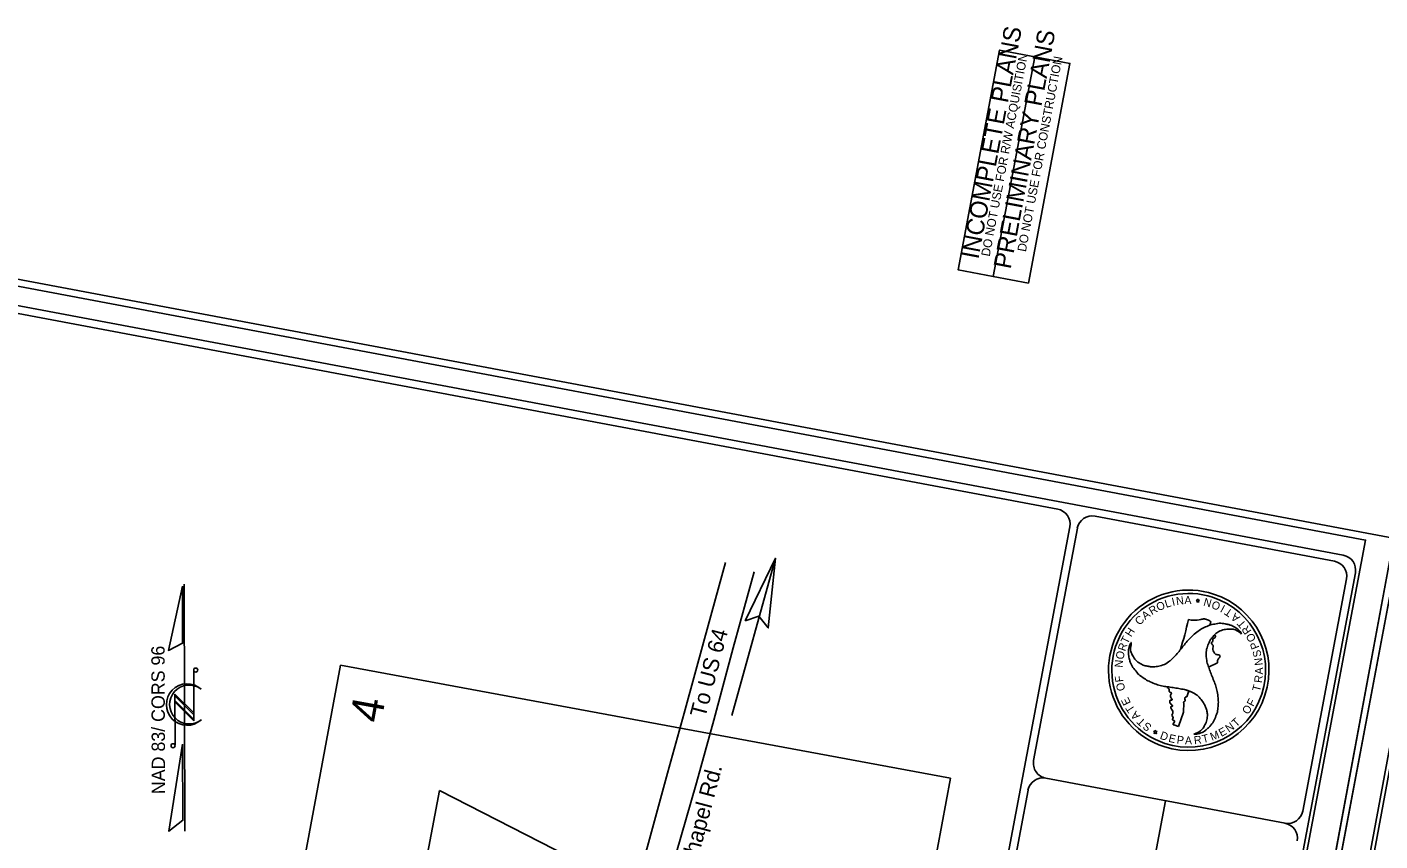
# Model space of a CAD drawing. Extents: x 1665923 to 1668724, y 690926 to 694920.
# Drawn here: x 1666413 to 1667302, y 692584 to 693119 of the extents above; entities that cross this region are included whole.
import ezdxf

# ---------------------------------------------------------------- set-up
doc = ezdxf.new("R2010")
doc.units = 0
for name, color, linetype in [('Default', 7, 'Continuous'), ('Prop Dimension Text', 7, 'Continuous'), ('Prop Horizontal Alignment Curve and Spiral Data', 7, 'Continuous'), ('Prop Terminator CELL', 7, 'Continuous'), ('Sheet Cutting Line CELL', 7, 'Continuous'), ('Sheet North Arrow CELL', 7, 'Continuous'), ('Sheet Plot Border Inside CELL', 7, 'Continuous'), ('Sheet Plot Border Outside CELL', 7, 'Continuous'), ('Sheet Sticker Incomplete CELL', 7, 'Continuous'), ('Sheet Sticker Preliminary CELL', 7, 'Continuous'), ('Sheet Symbology CELL', 7, 'Continuous'), ('Sheet Title CELL', 7, 'Continuous')]:
    doc.layers.add(name, color=color, linetype=linetype)

msp = doc.modelspace()

# ---------------------------------------------------------------- linework, layer by layer
at = {"layer": 'Default'}
for p, q in [((1666415.46, 691603.54), (1666618.88, 692699.33)), ((1666618.88, 692699.33), (1667019.7, 692624.93)), ((1667019.7, 692624.93), (1666816.29, 691529.13))]:
    msp.add_line(p, q, dxfattribs=at)
for points in [[(1666871.81, 692766.65), (1666858.14, 692716.44), (1666844.61, 692667.79), (1666833.67, 692628.16), (1666820.6, 692580), (1666808.36, 692536.32), (1666795.94, 692489.34), (1666787.41, 692455.82), (1666779.4, 692417.44), (1666773.85, 692389.02), (1666767.56, 692347.94), (1666763.59, 692314.54), (1666759.71, 692277.72), (1666756.73, 692243.18), (1666753.15, 692200.75), (1666749.37, 692166.77), (1666745.14, 692139.52)], [(1666890.65, 692760.64), (1666876.96, 692710.6), (1666864.1, 692663.19), (1666852.75, 692621.99), (1666839.29, 692574.85), (1666826.38, 692529.73), (1666814.57, 692484.35), (1666806.17, 692450.25), (1666798.26, 692414.12), (1666792.93, 692384.55), (1666786.89, 692344.99), (1666782.51, 692310.9), (1666779.03, 692275.93), (1666775.87, 692240.77), (1666772.32, 692199.18), (1666770.12, 692163.28), (1666768.85, 692135.98)]]:
    msp.add_lwpolyline(points, dxfattribs=at)
at = {"layer": 'Prop Dimension Text'}
msp.add_line((1666876.07, 692666.22), (1666904.6, 692769.48), dxfattribs=at)
at = {"layer": 'Prop Horizontal Alignment Curve and Spiral Data'}
for p, q in [((1666641.53, 692389.21), (1666683.8, 692616.91)), ((1666683.8, 692616.91), (1666821.26, 692546.76))]:
    msp.add_line(p, q, dxfattribs=at)
at = {"layer": 'Prop Terminator CELL'}
msp.add_lwpolyline([(1666884.84, 692728.31), (1666904.6, 692769.48), (1666899.93, 692723.77), (1666893.8, 692731.48)], close=True, dxfattribs=at)
at = {"layer": 'Sheet Cutting Line CELL'}
for p, q in [((1667310.99, 692782.59), (1667003.64, 691126.87)), ((1667003.64, 691126.87), (1667315.32, 692781.78))]:
    msp.add_line(p, q, dxfattribs=at)
at = {"layer": 'Sheet North Arrow CELL'}
for p, q in [((1666516.65, 692590.06), (1666516.05, 692752.56)), ((1666522.39, 692696.03), (1666522.51, 692662.68)), ((1666522.49, 692667.88), (1666510.02, 692680.26)), ((1666510.02, 692680.26), (1666510.14, 692646.36)), ((1666522.49, 692666.65), (1666510.02, 692679.03)), ((1666510.02, 692679.03), (1666510.03, 692675.98)), ((1666527.03, 692683.62), (1666527.21, 692683.5)), ((1666522.51, 692663.6), (1666510.03, 692675.98)), ((1666510.03, 692675.98), (1666522.51, 692663.6)), ((1666522.51, 692662.68), (1666510.04, 692675.06)), ((1666522.51, 692663.6), (1666522.49, 692666.65))]:
    msp.add_line(p, q, dxfattribs=at)
for points in [[(1666514.93, 692751.13), (1666505.81, 692708.89), (1666515.07, 692713.63)], [(1666515.12, 692647.3), (1666506.13, 692590.02), (1666515.3, 692597.3)]]:
    msp.add_lwpolyline(points, close=True, dxfattribs=at)
for centre in [(1666523.71, 692696.01), (1666508.82, 692646.3)]:
    msp.add_circle(centre, 1.32, dxfattribs=at)
for centre, radius, start, end in [((1666518.07, 692673.35), 13.65, 48.05248, 312.60651), ((1666519.39, 692673.36), 12.8, 53.30749, 308.84116)]:
    msp.add_arc(centre, radius, start, end, dxfattribs=at)
at = {"layer": 'Sheet Plot Border Inside CELL'}
for points in [[(1666983.99, 691143.8), (1667292.44, 692781.51), (1666255.57, 692976.79), (1665947.12, 691339.09)], [(1668065.46, 690942.99), (1668369.62, 692581.5), (1667332.24, 692774.07), (1667028.08, 691135.56)]]:
    msp.add_lwpolyline(points, close=True, dxfattribs=at)
at = {"layer": 'Sheet Plot Border Outside CELL'}
for points in [[(1666234.34, 692985.37), (1665922.65, 691330.47), (1667003.64, 691126.87), (1667315.32, 692781.78)], [(1668085.16, 690926.11), (1668392.51, 692581.83), (1667310.99, 692782.59), (1667003.64, 691126.87)]]:
    msp.add_lwpolyline(points, close=True, dxfattribs=at)
at = {"layer": 'Sheet Sticker Incomplete CELL'}
msp.add_lwpolyline([(1667047.81, 692954.72), (1667024.72, 692959.07), (1667051.92, 693103.53), (1667075.02, 693099.18)], close=True, dxfattribs=at)
at = {"layer": 'Sheet Sticker Preliminary CELL'}
msp.add_lwpolyline([(1667070.9, 692950.37), (1667047.81, 692954.72), (1667075.02, 693099.18), (1667098.11, 693094.83)], close=True, dxfattribs=at)
at = {"layer": 'Sheet Symbology CELL'}
msp.add_lwpolyline([(1667332.46, 692761.31), (1667058.7, 691286.51), (1668090.06, 691095.06), (1668363.83, 692569.86)], close=True, dxfattribs=at)
at = {"layer": 'Sheet Title CELL'}
for p, q in [((1666835.29, 691394.66), (1667098.11, 692790.12)), ((1667074.3, 692636.65), (1667103.03, 692789.2)), ((1667181.91, 692742.03), (1667181.01, 692741.99)), ((1667181.01, 692741.99), (1667181.72, 692741.46)), ((1667181.72, 692741.46), (1667181.44, 692740.6)), ((1667181.44, 692740.6), (1667182.18, 692741.15)), ((1667182.16, 692742.88), (1667181.91, 692742.03)), ((1667182.46, 692742.01), (1667182.16, 692742.88)), ((1667182.18, 692741.15), (1667182.93, 692740.62)), ((1667183.38, 692741.99), (1667182.46, 692742.01)), ((1667182.64, 692741.46), (1667183.38, 692741.99)), ((1667182.93, 692740.62), (1667182.64, 692741.46)), ((1667192.57, 692745.97), (1667192.57, 692745.97)), ((1667138.25, 692714.15), (1667138.32, 692714.02)), ((1667138.25, 692714.15), (1667138.32, 692714.02)), ((1667170.77, 692709.45), (1667170.77, 692709.45)), ((1667195.22, 692700.67), (1667189.29, 692697.96)), ((1667189.29, 692697.96), (1667189.29, 692697.96)), ((1667176.35, 692682.31), (1667175.01, 692678.36)), ((1667173.02, 692674.38), (1667172.84, 692668.4)), ((1667169.38, 692659.01), (1667166.4, 692660.1)), ((1667172.84, 692668.4), (1667169.38, 692659.01)), ((1667153.08, 692655.55), (1667153.98, 692655.58)), ((1667153.8, 692655.05), (1667153.08, 692655.55)), ((1667153.51, 692654.17), (1667153.8, 692655.05)), ((1667154.26, 692654.7), (1667153.51, 692654.17)), ((1667153.98, 692655.58), (1667154.26, 692656.44)), ((1667154.26, 692656.44), (1667154.54, 692655.56)), ((1667155.01, 692654.18), (1667154.26, 692654.7)), ((1667154.54, 692655.56), (1667155.46, 692655.56)), ((1667155.46, 692655.56), (1667154.71, 692655.01)), ((1667154.71, 692655.01), (1667155.01, 692654.18)), ((1667239.51, 692595.36), (1667082.27, 692624.97)), ((1667033.62, 692420.68), (1667070.6, 692617)), ((1667120.02, 692393.31), (1667160.87, 692610.17))]:
    msp.add_line(p, q, dxfattribs=at)
for points in [[(1667277.78, 692771.55), (1666265.59, 692962.19)], [(1667090.15, 692801.8), (1666269.57, 692956.35)], [(1667271.94, 692767.56), (1667114.71, 692797.18)], [(1667011.84, 691305.44), (1667285.77, 692759.87)], [(1667251.19, 692603.34), (1667279.92, 692755.88)]]:
    msp.add_lwpolyline(points, dxfattribs=at)
for centre, radius, start, end in [((1667088.24, 692791.99), 10, 349.33381, 79.33381), ((1667112.81, 692787.36), 10, 79.33381, 169.33381), ((1667270.05, 692757.75), 10, 349.33381, 79.33381), ((1667275.89, 692761.73), 10, 349.33381, 79.33381), ((1667176.21, 692695.87), 52.72, 71.90509, 251.90509), ((1667176.21, 692695.87), 50.52, 71.90509, 251.90509), ((1667176.21, 692695.87), 52.72, 251.90509, 71.90509), ((1667176.21, 692695.87), 50.52, 251.90509, 71.90509), ((1666904.94, 692790.61), 277.94, 343.02263, 347.22864), ((1666904.94, 692790.61), 277.94, 337.58358, 337.68318), ((1667084.12, 692634.8), 10, 169.33381, 259.33381), ((1667080.42, 692615.15), 10, 79.33381, 169.33381), ((1667241.3, 692605.2), 10, 259.33381, 349.33381), ((1667237.6, 692585.55), 10, 349.33381, 79.33381)]:
    msp.add_arc(centre, radius, start, end, dxfattribs=at)
for points in [[(1667210.99, 692719.64), (1667210.44, 692720.67), (1667208, 692723.21), (1667204.77, 692725.1), (1667204.44, 692725.26), (1667202.54, 692725.92), (1667200.21, 692726.4), (1667196.3, 692726.75), (1667192.38, 692726.11), (1667190.73, 692725.85), (1667188.97, 692725.14), (1667185.43, 692723.53), (1667182.35, 692721.6), (1667179.09, 692718.95), (1667176.4, 692716.42), (1667173.96, 692713.46), (1667171.59, 692710.45), (1667169.23, 692707.6), (1667166.71, 692704.63), (1667163.94, 692702.13), (1667163.67, 692701.94), (1667160.21, 692699.72), (1667156.51, 692698.6), (1667152.93, 692698.15), (1667151.12, 692698.22), (1667148.9, 692698.61), (1667147.61, 692698.79), (1667145.15, 692699.79), (1667142.07, 692701.91), (1667139.89, 692704.65), (1667138.41, 692707.52), (1667137.9, 692710.76), (1667138.32, 692714.02), (1667138.25, 692714.15)], [(1667190.07, 692725.65), (1667188.97, 692725.14), (1667185.43, 692723.53), (1667182.35, 692721.6), (1667179.09, 692718.95), (1667176.4, 692716.42), (1667173.96, 692713.46), (1667171.59, 692710.45), (1667170.77, 692709.45)], [(1667176.01, 692729.16), (1667179.59, 692728.78), (1667184.09, 692729.25), (1667186.62, 692729.67), (1667188.46, 692729.04), (1667190.54, 692727.88), (1667190.06, 692725.67)], [(1667179.49, 692653.87), (1667180.73, 692653.86), (1667184.13, 692654.7), (1667187.39, 692656.53), (1667187.63, 692656.77), (1667189.23, 692658.07), (1667190.76, 692659.84), (1667193.03, 692663.07), (1667194.43, 692666.76), (1667195.03, 692668.32), (1667195.3, 692670.26), (1667195.65, 692674.05), (1667195.53, 692677.67), (1667194.88, 692681.87), (1667194.05, 692685.42), (1667192.68, 692689.03), (1667191.23, 692692.59), (1667189.96, 692696.1), (1667188.7, 692699.72), (1667187.88, 692703.39), (1667187.85, 692703.77), (1667187.67, 692707.84), (1667188.53, 692711.57), (1667189.93, 692714.86), (1667190.88, 692716.51), (1667192.35, 692718.15), (1667193.15, 692719.22), (1667195.24, 692720.85), (1667198.59, 692722.4), (1667202.06, 692722.95), (1667205.32, 692722.81), (1667208.37, 692721.64), (1667210.99, 692719.64)], [(1667138.32, 692714.02), (1667137.66, 692712.99), (1667136.7, 692709.62), (1667136.68, 692705.88), (1667136.75, 692705.53), (1667137.08, 692703.55), (1667137.83, 692701.31), (1667139.51, 692697.75), (1667142, 692694.64), (1667143.08, 692693.37), (1667144.54, 692692.21), (1667147.71, 692689.95), (1667150.94, 692688.25), (1667154.86, 692686.72), (1667158.39, 692685.64), (1667162.16, 692685.05), (1667165.97, 692684.49), (1667169.64, 692683.87), (1667173.41, 692683.18), (1667177, 692682.02), (1667177.31, 692681.9), (1667180.91, 692680.02), (1667183.75, 692677.38), (1667185.91, 692674.47), (1667186.82, 692672.88), (1667187.57, 692670.77), (1667188.02, 692669.58), (1667188.44, 692666.92), (1667188.12, 692663.23), (1667186.83, 692659.94), (1667185.1, 692657.22), (1667182.57, 692655.15), (1667179.49, 692653.87)], [(1667189.29, 692697.96), (1667188.7, 692699.72), (1667187.88, 692703.39), (1667187.85, 692703.77), (1667187.67, 692707.84), (1667188.53, 692711.57), (1667189.93, 692714.86), (1667190.88, 692716.51), (1667192.35, 692718.15), (1667193.1, 692719.14)], [(1667193.11, 692719.12), (1667193.84, 692718.37), (1667193.65, 692717.59), (1667192.16, 692716.62), (1667191.96, 692714.89), (1667191.29, 692714.29), (1667191.11, 692713.8), (1667192.2, 692712.15), (1667192.03, 692710.43), (1667193.1, 692707.2), (1667194.04, 692706.3), (1667196.51, 692705.71), (1667196.77, 692704.92), (1667196.4, 692704.18), (1667195.26, 692702.78), (1667195.22, 692700.67)], [(1667166.4, 692660.1), (1667166.08, 692660.09), (1667165.92, 692660.7), (1667166.96, 692661.93), (1667166.59, 692662.84), (1667165.97, 692663.01), (1667165.54, 692663.77), (1667166.05, 692664.67), (1667165.22, 692665.91), (1667165.29, 692666.78), (1667165.85, 692668.47), (1667164.48, 692671.14), (1667164.64, 692672.02), (1667165.24, 692672.05), (1667165.52, 692672.54), (1667164.13, 692673.95), (1667163.97, 692674.25), (1667163.86, 692676.02), (1667164.29, 692676.34), (1667165.07, 692676.22), (1667165.3, 692676.39), (1667165.09, 692677.03), (1667164.43, 692678.02), (1667164.19, 692679.53), (1667164.84, 692680.95), (1667163.72, 692681.59), (1667163.13, 692683.69), (1667162.55, 692684.28), (1667161.86, 692684.6)], [(1667162.06, 692685.06), (1667162.16, 692685.05), (1667165.97, 692684.49), (1667169.64, 692683.87), (1667173.41, 692683.18), (1667176.35, 692682.3)], [(1667175.01, 692678.36), (1667174.16, 692678.21), (1667173.68, 692677.52), (1667173.89, 692676.3), (1667173.59, 692675.52), (1667172.69, 692674.87), (1667173.02, 692674.38)]]:
    msp.add_spline(points, degree=3, dxfattribs=at)

# ---------------------------------------------------------------- texts
at = {"layer": 'Prop Dimension Text'}
for s, height, rotation, p in [('To US 64', 10.5, 75.2455, (1666858.47, 692664.22)), ('4', 21, 79.7152, (1666645.49, 692660.6)), ('Bescher Chapel Rd.', 10.5, 75.2455, (1666837.81, 692511.02))]:
    msp.add_text(s, height=height, rotation=rotation, dxfattribs=at).set_placement(p)
at = {"layer": 'Sheet North Arrow CELL'}
msp.add_text('NAD 83/ CORS 96', height=8.75, rotation=90.21245, dxfattribs=at).set_placement((1666503.63, 692614.5))
at = {"layer": 'Sheet Sticker Incomplete CELL'}
for s, height, p in [('INCOMPLETE PLANS', 11.52, (1667037.97, 692965.68)), ('DO NOT USE FOR R/W ACQUISITION', 5.76, (1667045.4, 692967.59))]:
    msp.add_text(s, height=height, rotation=79.33381, dxfattribs=at).set_placement(p)
at = {"layer": 'Sheet Sticker Preliminary CELL'}
for s, height, p in [('PRELIMINARY PLANS', 11.52, (1667059.18, 692959.19)), ('DO NOT USE FOR CONSTRUCTION', 5.76, (1667069.18, 692970.64))]:
    msp.add_text(s, height=height, rotation=79.33381, dxfattribs=at).set_placement(p)
at = {"layer": 'Sheet Title CELL'}
for s, height, rotation, p in [('O', 5.27, 23.72354, (1667156.26, 692734.61)), ('L', 5.24, 17.48987, (1667161.38, 692736.86)), ('I', 5.26, 13.50052, (1667165.75, 692738.14)), ('N', 5.25, 7.80042, (1667168.25, 692738.7)), ('A', 5.26, 0.36844, (1667173.36, 692739.36)), ('N', 5.26, 164.11322, (1667191.8, 692742.2)), ('O', 5.24, 156.8652, (1667197.66, 692739.76)), ('C', 5.24, 44.70413, (1667143.9, 692725.1)), ('A', 5.25, 37.20709, (1667147.65, 692728.78)), ('R', 5.25, 30.84315, (1667151.94, 692732.04)), ('I', 5.27, 151.72958, (1667200.64, 692738.19)), ('T', 5.25, 146.07967, (1667205.58, 692734.9)), ('A', 5.27, 138.99524, (1667210.33, 692730.86)), ('H', 5.25, 57.04647, (1667138.32, 692717.39)), ('T', 5.24, 130.9082, (1667214.31, 692726.43)), ('R', 5.26, 124.80841, (1667217.69, 692721.69)), ('R', 5.26, 70.78083, (1667134.39, 692708.03)), ('T', 5.27, 64.13119, (1667136.04, 692712.78)), ('O', 5.27, 117.61931, (1667220.67, 692716.08)), ('P', 5.25, 110.92731, (1667222.73, 692710.84)), ('O', 5.27, 77.39075, (1667133.18, 692702.6)), ('S', 5.23, 103.73546, (1667224.14, 692705.2)), ('N', 5.26, 84.88886, (1667132.69, 692697.49)), ('N', 5.24, 96.52499, (1667224.92, 692699.3)), ('A', 5.24, 89.49336, (1667224.97, 692693.09)), ('F', 5.27, 96.9758, (1667133.31, 692688.36)), ('O', 5.26, 104.12264, (1667134.63, 692682.96)), ('T', 5.24, 75.78361, (1667222.91, 692681.53)), ('R', 5.26, 82.74023, (1667224.31, 692687.32)), ('E', 5.24, 116.06202, (1667138.31, 692674.39)), ('T', 5.24, 123.17765, (1667141.11, 692670.08)), ('A', 5.27, 130.23287, (1667144.62, 692665.92)), ('O', 5.25, 55.70915, (1667215.13, 692666.37)), ('F', 5.25, 62.87438, (1667218.64, 692671.67)), ('T', 5.27, 137.28518, (1667148.34, 692662.39)), ('S', 5.25, 143.66134, (1667152.37, 692659.41)), ('N', 5.27, 35.56347, (1667202.58, 692654.77)), ('T', 5.25, 42.40547, (1667207.37, 692658.27)), ('D', 5.26, 339.75808, (1667156.86, 692651.04)), ('E', 5.23, 346.04597, (1667162.54, 692649)), ('P', 5.26, 353.57837, (1667168.11, 692647.73)), ('A', 5.25, 0.17094, (1667173.69, 692647.1)), ('R', 5.26, 7.23958, (1667179.92, 692647.19)), ('T', 5.25, 13.89011, (1667185.66, 692647.97)), ('M', 5.24, 21.12515, (1667191.44, 692649.49)), ('E', 5.24, 28.59193, (1667197.63, 692652))]:
    msp.add_text(s, height=height, rotation=rotation, dxfattribs=at).set_placement(p)

doc.saveas('drawing.dxf')
